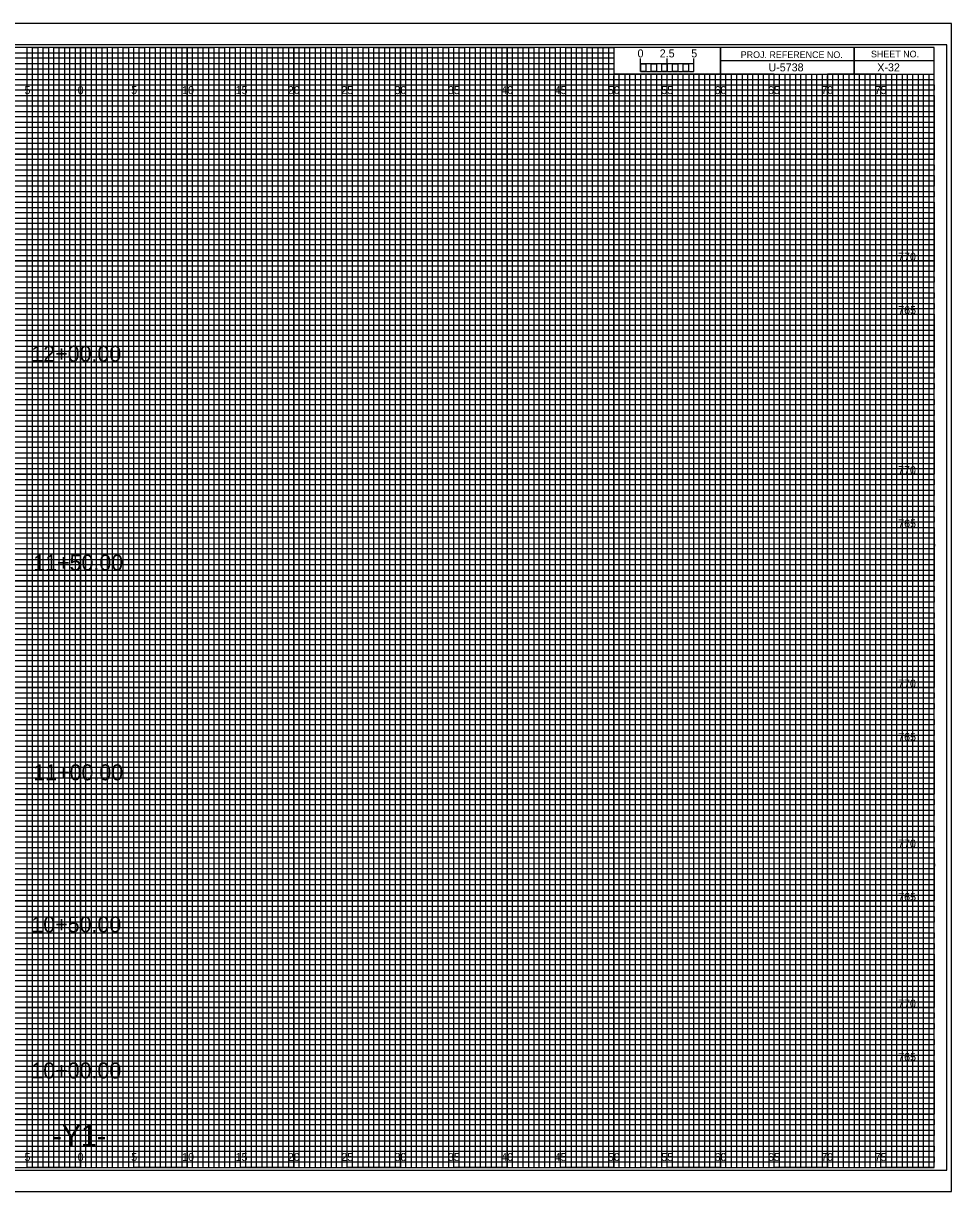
# Model space of a CAD drawing. Extents: x -7 to 162, y -2 to 107.
# Drawn here: x 74.6 to 161.7, y -2.3 to 107.3 of the extents above; entities that cross this region are included whole.
import ezdxf

# ---------------------------------------------------------------- set-up
doc = ezdxf.new("R2010")
doc.units = 0
for name, color, linetype in [('Exist Cross Section Cell', 7, 'Continuous'), ('Exist XS Center Line Elevation Label', 7, 'Continuous'), ('Exist XS Ground Line', 7, 'Continuous'), ('Old_Level_63', 7, 'Continuous'), ('Prop CMT Pvmt Course 1', 7, 'Continuous'), ('Prop CMT Pvmt Course 1 CG', 7, 'Continuous'), ('Prop XS Alignment Label', 7, 'Continuous'), ('Prop XS Bar Scale Labels', 7, 'Continuous'), ('Prop XS Elevation Labels', 7, 'Continuous'), ('Prop XS Project Number', 7, 'Continuous'), ('Prop XS Sheet Number', 7, 'Continuous'), ('Prop XS Station Labels', 7, 'Continuous'), ('Prop XSC Text', 7, 'Continuous'), ('Sheet Cross Section Grid Major CELL', 7, 'Continuous'), ('Sheet Cross Section Grid Minor 2 CELL', 7, 'Continuous'), ('Sheet Cutting Line CELL', 7, 'Continuous'), ('Sheet DOT Grid CELL', 7, 'Continuous')]:
    doc.layers.add(name, color=color, linetype=linetype)

msp = doc.modelspace()

# ---------------------------------------------------------------- linework, layer by layer
at = {"layer": 'Exist Cross Section Cell'}
for p, q in [((132.5, 102.75), (132.5, 103.95)), ((132.5, 103.45), (132.5, 103.95)), ((135, 102.75), (135, 103.95)), ((137.5, 102.75), (137.5, 103.95)), ((137.5, 103.45), (137.5, 103.95))]:
    msp.add_line(p, q, dxfattribs=at)
for points in [[(137.5, 103.45), (132.5, 103.45), (132.5, 102.75), (137.5, 102.75)], [(132.5, 103.45), (133, 103.45), (133, 102.75), (132.5, 102.75)], [(133.5, 103.45), (134, 103.45), (134, 102.75), (133.5, 102.75)], [(134.5, 103.45), (135, 103.45), (135, 102.75), (134.5, 102.75)], [(135.5, 103.45), (136, 103.45), (136, 102.75), (135.5, 102.75)], [(136.5, 103.45), (137, 103.45), (137, 102.75), (136.5, 102.75)]]:
    msp.add_lwpolyline(points, close=True, dxfattribs=at)
at = {"layer": 'Exist XS Center Line Elevation Label'}
msp.add_lwpolyline([(-5.4, -0.25), (161.2, -0.25), (161.2, 105.25), (-5.4, 105.25)], close=True, dxfattribs=at)
at = {"layer": 'Exist XS Ground Line'}
msp.add_lwpolyline([(-6.7, -2.25), (161.65, -2.25), (161.65, 107.25), (-6.7, 107.25)], close=True, dxfattribs=at)
at = {"layer": 'Old_Level_63'}
for p, q in [((152.5, 105), (152.5, 102.5)), ((152.5, 102.5), (152.5, 105)), ((160, 103.75), (140, 103.75)), ((140, 103.75), (140, 102.5)), ((140, 102.5), (160, 102.5))]:
    msp.add_line(p, q, dxfattribs=at)
for points in [[(160, 105), (0, 105), (0, 0), (160, 0)], [(140, 105), (130, 105), (130, 102.52), (140, 102.52)], [(160, 105), (140, 105), (140, 102.5), (160, 102.5)]]:
    msp.add_lwpolyline(points, close=True, dxfattribs=at)
at = {"layer": 'Prop CMT Pvmt Course 1'}
for points in [[(72.5, 0), (77.5, 0), (77.5, 105), (82.5, 105), (82.5, 0), (87.5, 0), (87.5, 105), (92.5, 105), (92.5, 0), (97.5, 0), (97.5, 105), (102.5, 105), (102.5, 0), (107.5, 0), (107.5, 105), (112.5, 105), (112.5, 0), (117.5, 0), (117.5, 105), (122.5, 105), (122.5, 0), (127.5, 0), (127.5, 105), (129.97, 105), (130, 105), (130, 102.5), (132.5, 102.5), (132.5, 0), (137.5, 0), (137.5, 102.5), (142.5, 102.5), (142.5, 0), (147.5, 0), (147.5, 102.5), (152.5, 102.5), (152.5, 0), (157.5, 0), (157.5, 102.5)], [(0, 102.5), (137.5, 102.5)], [(0, 92.5), (160, 92.5), (160, 97.5), (0, 97.5)], [(0, 82.5), (160, 82.5), (160, 87.5), (0, 87.5)], [(0, 72.5), (160, 72.5), (160, 77.5), (0, 77.5)], [(0, 62.5), (160, 62.5), (160, 67.5), (0, 67.5)], [(0, 52.5), (160, 52.5), (160, 57.5), (0, 57.5)], [(0, 42.5), (160, 42.5), (160, 47.5), (0, 47.5)], [(0, 32.5), (160, 32.5), (160, 37.5), (0, 37.5)], [(0, 22.5), (160, 22.5), (160, 27.5), (0, 27.5)], [(0, 12.5), (160, 12.5), (160, 17.5), (0, 17.5)], [(0, 2.5), (160, 2.5), (160, 7.5), (0, 7.5)]]:
    msp.add_lwpolyline(points, dxfattribs=at)
at = {"layer": 'Prop XSC Text'}
for p, q in [((0, 104.5), (130, 104.5)), ((130, 104.5), (130, 103.99)), ((130, 103.99), (0, 103.99)), ((0, 103.5), (130, 103.5)), ((130, 102.95), (0, 102.95)), ((130, 103.5), (130, 102.95)), ((0, 102), (160, 102))]:
    msp.add_line(p, q, dxfattribs=at)
for points in [[(0, 101.5), (135, 101.5), (160, 101.5), (160, 101), (0, 101)], [(0, 100.5), (160, 100.5), (160, 99.5), (0, 99.5)], [(0, 99), (160, 99), (160, 98.5), (0, 98.49)], [(0, 98), (160, 98), (160, 97), (0, 97)], [(0, 96.5), (160, 96.5), (160, 96), (0, 96)], [(0, 95.5), (160, 95.5), (160, 94.5), (0, 94.5)], [(0, 94), (160, 94), (160, 93.5), (0, 93.5)], [(0, 93), (160, 93), (160, 92), (0, 92)], [(0, 91.5), (160, 91.5), (160, 91), (0, 91)], [(0, 90.5), (160, 90.5), (160, 89.5), (0, 89.5)], [(0, 89), (160, 89), (160, 88.5), (0, 88.5)], [(0, 88), (160, 88), (160, 86.98), (160, 86.5), (160, 86), (0, 86)], [(0, 87), (160, 87), (160, 86.5), (0, 86.5)], [(0, 85.5), (160, 85.5), (160, 84.5), (0, 84.52)], [(0, 84.52), (160, 84.5), (160, 84), (0, 84)], [(0, 83.5), (160, 83.5), (160, 83), (0, 83)], [(0, 82), (160, 82), (160, 81.5), (0, 81.5)], [(0, 81), (160, 81), (160, 80.5), (0, 80.5)], [(-0.04, 79.45), (160, 79.45), (160, 78.94), (-0.04, 78.94)], [(0, 78.5), (160, 78.5), (160, 78), (0, 78)], [(0, 77), (160, 77), (160, 76.5), (0, 76.5)], [(0, 76), (160, 76), (160, 75.5), (0, 75.5)], [(0, 74.5), (160, 74.5), (160, 74), (0, 74)], [(0, 73.5), (160, 73.5), (160, 73), (0, 73)], [(0, 72), (160, 72), (160, 71.5), (0, 71.5)], [(0, 71), (160, 71), (160, 70.5), (0, 70.5)], [(0, 69.5), (160, 69.5), (160, 68.99), (0, 69)], [(0, 68.5), (160, 68.5), (160, 68), (0, 68)], [(0, 67), (160, 67), (160, 66.5), (0, 66.5)], [(0, 66), (160, 66), (160, 65.5), (0, 65.5)], [(0, 64.5), (160, 64.5), (160, 64), (0, 64)], [(0, 63.5), (160, 63.5), (160, 63), (0, 63)], [(0, 62), (160, 62), (160, 61.5), (0, 61.5)], [(0, 61), (160, 61), (160, 60.5), (0, 60.5)], [(0, 59.5), (160, 59.5), (160, 59), (0, 59)], [(0, 58.5), (160.03, 58.45), (160, 58), (0, 58)], [(0, 57), (160, 57), (160, 56.5), (0, 56.5)], [(0, 56), (160, 56), (160, 55.5), (0, 55.5)], [(0, 54.5), (160, 54.5), (160, 54), (0, 54)], [(0, 53.5), (160, 53.5), (160, 53), (0, 53)], [(0, 52), (160, 52), (160, 51.5), (0, 51.5)], [(0, 51), (160, 51), (160, 50.5), (0, 50.5)], [(0, 49.5), (160, 49.5), (160, 49), (0, 49)], [(0, 48.5), (160, 48.5), (160, 48), (0, 48)], [(0, 47), (160, 47), (160, 46.5), (0, 46.5)], [(0, 46), (160, 46), (160, 45.5), (0, 45.5)], [(0, 44.5), (160, 44.5), (160, 44), (0, 44)], [(0, 43.5), (160, 43.5), (160, 43), (0, 43)], [(0, 42), (160, 42), (160, 41.5), (0, 41.5)], [(0, 41), (160, 41), (160, 40.5), (0, 40.5)], [(0, 39.5), (160, 39.5), (160, 38.99), (0, 39)], [(0, 38.5), (160, 38.5), (160, 38), (0, 38)], [(0, 37), (160, 37), (160, 36.5), (0, 36.5)], [(0, 36), (160, 36), (160, 35.5), (0, 35.5)], [(0, 34.5), (160, 34.5), (160, 34), (0, 34)], [(0, 33.5), (160, 33.5), (160, 33), (0, 33)], [(0, 32), (160, 32), (160, 31.5), (0, 31.5)], [(0, 31), (160, 31), (160, 30.5), (0, 30.5)], [(0, 29.5), (160, 29.5), (160, 29), (0, 29)], [(0, 28.5), (160.03, 28.46), (160, 28), (0, 28)], [(0, 27), (160, 27), (160, 26.5), (0, 26.5)], [(0, 26), (160, 26), (160, 25.5), (0, 25.5)], [(0, 24.5), (160, 24.5), (160, 24), (0, 24)], [(0, 23.5), (160, 23.5), (160, 23), (0, 23)], [(0, 22), (160, 22), (160, 21.5), (0, 21.5)], [(0, 21), (160, 21), (160, 20.5), (0, 20.5)], [(0, 19.5), (160, 19.5), (160, 19), (0, 19)], [(0, 18.5), (160, 18.5), (160, 18), (0, 18)], [(0, 17), (160, 17), (160, 16.5), (0, 16.5)], [(0, 16), (160, 16), (160, 15.5), (0, 15.5)], [(0, 14.5), (160, 14.5), (160, 14), (0, 14)], [(0, 13.5), (160, 13.5), (160, 13), (0, 13)], [(0, 12), (160, 12), (160, 11.5), (0, 11.5)], [(0, 11), (160, 11), (160, 10.5), (0, 10.5)], [(0, 9.5), (160, 9.5), (160, 9), (0, 9)], [(0, 8.5), (160, 8.5), (160, 8), (0, 8)], [(0, 7), (160, 7), (160, 6.5), (0, 6.5)], [(0, 6), (160, 6), (160, 5.5), (0, 5.5)], [(0, 4.5), (160, 4.5), (160, 4), (0, 4)], [(0, 3.5), (160, 3.5), (160, 3), (0, 3)], [(0, 2), (160, 2), (160, 1.5), (0, 1.5)], [(0, 1), (160, 1), (160, 0.5), (0, 0.5)]]:
    msp.add_lwpolyline(points, dxfattribs=at)
at = {"layer": 'Sheet Cross Section Grid Major CELL'}
for p, q in [((75, 105), (70, 105)), ((75, 0), (75, 105)), ((85, 105), (80, 105)), ((80, 105), (80, 0)), ((85, 0), (85, 105)), ((95, 105), (90, 105)), ((90, 105), (90, 0)), ((95, 0), (95, 105)), ((105, 105), (100, 105)), ((100, 105), (100, 0)), ((105, 0), (105, 105)), ((115, 105), (110, 105)), ((110, 105), (110, 0)), ((115, 0), (115, 105)), ((125, 105), (120, 105)), ((120, 105), (120, 0)), ((125, 0), (125, 105)), ((130, 105), (130, 0)), ((135, 0), (135, 102.5)), ((145, 102.5), (140, 102.5)), ((140, 102.5), (140, 0)), ((145, 0), (145, 102.5)), ((155, 102.5), (150, 102.5)), ((150, 102.5), (150, 0)), ((155, 0), (155, 102.5)), ((80, 0), (75, 0)), ((90, 0), (85, 0)), ((100, 0), (95, 0)), ((110, 0), (105, 0)), ((120, 0), (115, 0)), ((130, 0), (125, 0)), ((140, 0), (135, 0)), ((150, 0), (145, 0)), ((160, 0), (155, 0)), ((160, 0), (160, 0))]:
    msp.add_line(p, q, dxfattribs=at)
for points in [[(0, 100), (160, 100), (160, 95), (0, 95)], [(0, 90), (160, 90), (160, 85), (0, 85)], [(0, 80), (160, 80), (160, 75), (0, 75)], [(0, 70), (160, 70), (160, 65), (0, 65)], [(0, 60), (160, 60), (160, 55), (0, 55)], [(0, 50), (160, 50), (160, 45), (0, 45)], [(0, 40), (160, 40), (160, 35), (0, 35)], [(0, 30), (160, 30), (160, 25), (0, 25)], [(0, 20), (160, 20), (160, 15), (0, 15)], [(0, 10), (160, 10), (160, 5), (0, 5)]]:
    msp.add_lwpolyline(points, dxfattribs=at)
at = {"layer": 'Sheet Cross Section Grid Minor 2 CELL'}
for p, q in [((133.5, 102.5), (133, 102.5)), ((133, 102.5), (133, 0)), ((133.5, 0), (133.5, 102.5)), ((134.5, 102.5), (134, 102.5)), ((134, 102.5), (134, 0)), ((134.5, 0), (134.5, 102.5)), ((133, 0), (132.5, 0)), ((134, 0), (133.5, 0))]:
    msp.add_line(p, q, dxfattribs=at)
for points in [[(75, 0), (75.5, 0), (75.5, 105), (76, 105), (76, 0)], [(76, 0), (76.5, 0), (76.5, 105), (77, 105), (77, 0)], [(77.5, 0), (78, 0), (78, 105), (78.5, 105), (78.5, 0)], [(78.5, 0), (79, 0), (79, 105), (79.5, 105), (79.5, 0)], [(80, 0), (80.5, 0), (80.5, 105), (81, 105), (81, 0)], [(81, 0), (81.5, 0), (81.5, 105), (82, 105), (82, 0)], [(82.5, 0), (83, 0), (83, 105), (83.5, 105), (83.5, 0)], [(83.5, 0), (84, 0), (84, 105), (84.5, 105), (84.5, 0)], [(85, 0), (85.5, 0), (85.5, 105), (86, 105), (86, 0)], [(86, 0), (86.5, 0), (86.5, 105), (87, 105), (87, 0)], [(87.5, 0), (88, 0), (88, 105), (88.5, 105), (88.5, 0)], [(88.5, 0), (89, 0), (89, 105), (89.5, 105), (89.5, 0)], [(90, 0), (90.5, 0), (90.5, 105), (91, 105), (91, 0)], [(91, 0), (91.5, 0), (91.5, 105), (92, 105), (92, 0)], [(92.5, 0), (93, 0), (93, 105), (93.5, 105), (93.5, 0)], [(93.5, 0), (94, 0), (94, 105), (94.5, 105), (94.5, 0)], [(95, 0), (95.5, 0), (95.5, 105), (96, 105), (96, 0)], [(96, 0), (96.5, 0), (96.5, 105), (97, 105), (97, 0)], [(97.5, 0), (98, 0), (98, 105), (98.5, 105), (98.5, 0)], [(98.5, 0), (99, 0), (99, 105), (99.5, 105), (99.5, 0)], [(100, 0), (100.5, 0), (100.5, 105), (101, 105), (101, 0)], [(101, 0), (101.5, 0), (101.5, 105), (102, 105), (102, 0)], [(102.5, 0), (103, 0), (103, 105), (103.5, 105), (103.5, 0)], [(103.5, 0), (104, 0), (104, 105), (104.5, 105), (104.5, 0)], [(105, 0), (105.5, 0), (105.5, 105), (106, 105), (106, 0)], [(106, 0), (106.5, 0), (106.5, 105), (107, 105), (107, 0)], [(107.5, 0), (108, 0), (108, 105), (108.5, 105), (108.5, 0)], [(108.5, 0), (109, 0), (109, 105), (109.5, 105), (109.5, 0)], [(110, 0), (110.5, 0), (110.5, 105), (111, 105), (111, 0)], [(111, 0), (111.5, 0), (111.5, 105), (112, 105), (112, 0)], [(112.5, 0), (113, 0), (113, 105), (113.5, 105), (113.5, 0)], [(113.5, 0), (114, 0), (114, 105), (114.5, 105), (114.5, 0)], [(115, 0), (115.5, 0), (115.5, 105), (116, 105), (116, 0)], [(116, 0), (116.5, 0), (116.5, 105), (117, 105), (117, 0)], [(117.5, 0), (118, 0), (118, 105), (118.5, 105), (118.5, 0)], [(118.5, 0), (119, 0), (119, 105), (119.5, 105), (119.5, 0)], [(120, 0), (120.5, 0), (120.5, 105), (121, 105), (121, 0)], [(121, 0), (121.5, 0), (121.5, 105), (122, 105), (122, 0)], [(122.5, 0), (123, 0), (123, 105), (123.5, 105), (123.5, 0)], [(123.5, 0), (124, 0), (124, 105), (124.5, 105), (124.5, 0)], [(125, 0), (125.5, 0), (125.5, 105), (126, 105), (126, 0)], [(126, 0), (126.5, 0), (126.5, 105), (127, 105), (127, 0)], [(127.5, 0), (128, 0), (128, 105), (128.5, 105), (128.5, 0)], [(128.5, 0), (129, 0), (129, 105), (129.5, 105), (129.5, 0)], [(130, 0), (130.5, 0), (130.5, 102.5), (131.01, 102.5), (131.01, 0)], [(131, 0), (131.5, 0), (131.5, 102.5), (132, 102.5), (132, 0)], [(135, 0), (135.49, 0), (135.49, 102.5), (136, 102.5), (136, 0)], [(136, 0), (136.5, 0), (136.5, 102.5), (137.03, 102.5), (137.03, 0)], [(137.5, 0), (138, 0), (138, 102.5), (138.5, 102.5), (138.5, 0)], [(138.5, 0), (139, 0), (139, 102.5), (139.5, 102.5), (139.5, 0)], [(140, 0), (140.5, 0), (140.5, 102.5), (141, 102.5), (141, 0)], [(141, 0), (141.5, 0), (141.5, 102.5), (142, 102.5), (142, 0)], [(142.5, 0), (143, 0), (143, 102.5), (143.5, 102.5), (143.5, 0)], [(143.5, 0), (144, 0), (144, 102.5), (144.5, 102.5), (144.5, 0)], [(145, 0), (145.5, 0), (145.5, 102.5), (146, 102.5), (146, 0)], [(146, 0), (146.5, 0), (146.5, 102.5), (147, 102.5), (147, 0)], [(147.5, 0), (148, 0), (148, 102.5), (148.5, 102.5), (148.5, 0)], [(148.5, 0), (149, 0), (149, 102.5), (149.5, 102.5), (149.5, 0)], [(150, 0), (150.5, 0), (150.5, 102.5), (151, 102.5), (151, 0)], [(151, 0), (151.5, 0), (151.5, 102.5), (152, 102.5), (152, 0)], [(152.5, 0), (153, 0), (153, 102.5), (153.5, 102.5), (153.5, 0)], [(153.5, 0), (154, 0), (154, 102.5), (154.5, 102.5), (154.5, 0)], [(155, 0), (155.5, 0), (155.5, 102.5), (156, 102.5), (156, 0)], [(156, 0), (156.5, 0), (156.5, 102.5), (157, 102.5), (157, 0)], [(157.5, 0), (158, 0), (158, 102.5), (158.5, 102.5), (158.5, 0)], [(158.5, 0), (159, 0), (159, 102.5), (159.5, 102.5), (159.5, 0)]]:
    msp.add_lwpolyline(points, dxfattribs=at)
at = {"layer": 'Sheet Cutting Line CELL'}
for p, q in [((161.65, 107.25), (-6.7, 107.25)), ((-6.7, -2.25), (161.65, -2.25))]:
    msp.add_line(p, q, dxfattribs=at)
at = {"layer": 'Sheet DOT Grid CELL'}
for p, q in [((75, 0), (75, 105)), ((80, 0), (80, 105)), ((85, 0), (85, 105)), ((90, 0), (90, 105)), ((95, 0), (95, 105)), ((100, 0), (100, 105)), ((105, 0), (105, 105)), ((110, 0), (110, 105)), ((115, 0), (115, 105)), ((120, 0), (120, 105)), ((125, 0), (125, 105)), ((130, 0), (130, 102.34)), ((135, 0), (135, 102.34)), ((140, 0), (140, 102.34)), ((145, 0), (145, 102.34)), ((150, 0), (150, 102.34)), ((155, 0), (155, 102.34)), ((0, 100), (160, 100)), ((0, 95), (160, 95)), ((0, 90), (160, 90)), ((0, 85), (160, 85)), ((0, 80), (160, 80)), ((0, 75), (160, 75)), ((0, 70), (160, 70)), ((0, 65), (160, 65)), ((0, 60), (160, 60)), ((0, 55), (160, 55)), ((0, 50), (160, 50)), ((0, 45), (160, 45)), ((0, 40), (160, 40)), ((0, 35), (160, 35)), ((0, 30), (160, 30)), ((0, 25), (160, 25)), ((0, 20), (160, 20)), ((0, 15), (160, 15)), ((0, 10), (160, 10)), ((0, 5), (160, 5))]:
    msp.add_line(p, q, dxfattribs=at)

# ---------------------------------------------------------------- texts
at = {"layer": 'Exist Cross Section Cell'}
msp.add_text('0', height=0.75, dxfattribs=at).set_placement((132.21, 104.06))
at = {"layer": 'Old_Level_63'}
for s, p in [('PROJ. REFERENCE NO.', (141.88, 104)), ('SHEET NO.', (154.09, 104.06))]:
    msp.add_text(s, height=0.625, dxfattribs=at).set_placement(p)
at = {"layer": 'Prop CMT Pvmt Course 1 CG'}
for s, p in [('5', (74.74, 100.62)), ('0', (79.73, 100.62)), ('0', (79.73, 100.62)), ('5', (84.74, 100.62)), ('10', (89.52, 100.62)), ('15', (94.53, 100.62)), ('20', (99.43, 100.62)), ('25', (104.44, 100.62)), ('30', (109.43, 100.62)), ('35', (114.44, 100.62)), ('40', (119.43, 100.62)), ('45', (124.44, 100.62)), ('50', (129.43, 100.62)), ('55', (134.44, 100.62)), ('60', (139.43, 100.62)), ('65', (144.44, 100.62)), ('70', (149.43, 100.62)), ('75', (154.44, 100.62)), ('5', (74.74, 0.62)), ('0', (79.73, 0.62)), ('0', (79.73, 0.62)), ('5', (84.74, 0.62)), ('10', (89.52, 0.62)), ('15', (94.53, 0.62)), ('20', (99.43, 0.62)), ('25', (104.44, 0.62)), ('30', (109.43, 0.62)), ('35', (114.44, 0.62)), ('40', (119.43, 0.62)), ('45', (124.44, 0.62)), ('50', (129.43, 0.62)), ('55', (134.44, 0.62)), ('60', (139.43, 0.62)), ('65', (144.44, 0.62)), ('70', (149.43, 0.62)), ('75', (154.44, 0.62))]:
    msp.add_text(s, height=0.75, dxfattribs=at).set_placement(p)
at = {"layer": 'Prop XS Alignment Label'}
msp.add_text('-Y1-', height=2, dxfattribs=at).set_placement((77.36, 2))
at = {"layer": 'Prop XS Bar Scale Labels'}
for s, p in [('2.5', (134.29, 104.06)), ('5', (137.24, 104.06))]:
    msp.add_text(s, height=0.75, dxfattribs=at).set_placement(p)
at = {"layer": 'Prop XS Elevation Labels'}
for s, p in [('770', (156.63, 85)), ('765', (156.64, 80)), ('770', (156.63, 65)), ('765', (156.64, 60)), ('770', (156.63, 45)), ('765', (156.64, 40)), ('770', (156.63, 30)), ('765', (156.64, 25)), ('770', (156.63, 15)), ('765', (156.64, 10))]:
    msp.add_text(s, height=0.75, dxfattribs=at).set_placement(p)
at = {"layer": 'Prop XS Project Number'}
msp.add_text('U-5738', height=0.75, dxfattribs=at).set_placement((144.48, 102.75))
at = {"layer": 'Prop XS Sheet Number'}
msp.add_text('X-32', height=0.75, dxfattribs=at).set_placement((154.68, 102.75))
at = {"layer": 'Prop XS Station Labels'}
for s, p in [('12+00.00', (75.39, 75.54)), ('11+50.00', (75.57, 55.96)), ('11+00.00', (75.57, 36.3)), ('10+50.00', (75.39, 22.05)), ('10+00.00', (75.39, 8.36))]:
    msp.add_text(s, height=1.5, dxfattribs=at).set_placement(p)

doc.saveas('drawing.dxf')
